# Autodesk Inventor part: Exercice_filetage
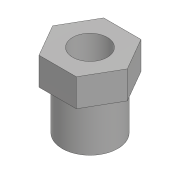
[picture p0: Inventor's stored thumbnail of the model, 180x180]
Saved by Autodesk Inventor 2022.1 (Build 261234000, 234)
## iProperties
Created: 2018-06
Part Number: Exercice_filetage
Material: Générique
Document SubType Name: Modeling
Designer: Fabian Perrée
Density: 1 g/cm^3
Appearance: Gris clair
Mass: 1.44256 g
Surface Area: 12.9609 cm^2
Volume: 1.44256 cm^3
Author: Fabian Perrée
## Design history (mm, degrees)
sketch "Esquisse1"
  geometry: C1 r 6 at (0, 0); C2 r 3.75 at (0, 0); 1 further point
  constraints: 2 centre point, 2 coincident
  dimensions: "d0" = 12 diameter of C1; "d1" = 7.5 diameter of C2
extrude "Extrusion1" new body sketch "Esquisse1" distance "d2" = 16; taper "d3" = 0 deg
sketch "Esquisse2"
  geometry: L1 (4.041, -7)-(-4.041, -7); L2 (-4.041, -7)-(-8.083, 0); L3 (-8.083, 0)-(-4.041, 7); L4 (-4.041, 7)-(4.041, 7); L5 (4.041, 7)-(8.083, 0); L6 (8.083, 0)-(4.041, -7); C1 r 3.75 at (0, 0) reference; C2 r 6 at (0, 0) reference; 1 further point
  constraints: 12 end point, 1 coincident, 1 horizontal, 13 other
  dimensions: "d4" = 14 distance between parallel lines of L4 L1
extrude "Extrusion2" join sketch "Esquisse2" distance "d5" = 6; taper "d6" = 0 deg
node "Solide1"
